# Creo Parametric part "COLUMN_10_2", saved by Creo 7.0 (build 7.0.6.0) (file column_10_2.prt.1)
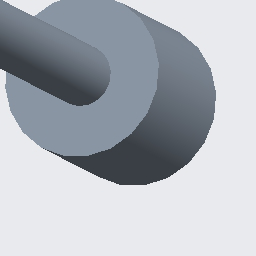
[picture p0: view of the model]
Units: millimeter Newton Second (mmNs); MM, TONNE, SECS

Created from: XX_MMNS_PART_SOLID_ABS.PRT

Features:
  1. datum plane "RIGHT"
  2. datum plane "TOP"
  3. datum plane "FRONT"
  4. coordinate system
  5. extrusion "Extrude 1"
  6. extruded cut "Extrude 2"
  7. extrusion "Extrude 3"

Surfaces: 4 plane, 3 cylinder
